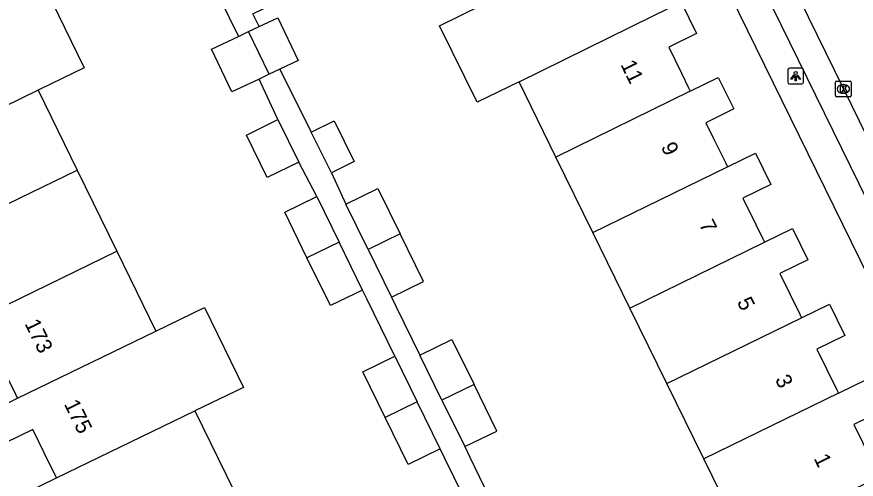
# Model space of a CAD drawing. Extents: x 160457 to 162082, y 388340 to 389736.
# Drawn here: x 160940.3 to 160994.2, y 388958.7 to 388988.4 of the extents above; entities that cross this region are included whole.
import ezdxf

# ---------------------------------------------------------------- set-up
doc = ezdxf.new("R2010")
doc.units = 0
for name, color, linetype in [('IMGEO_Kolk', 7, 'Continuous'), ('IMGEO_Lichtpunt', 7, 'Continuous'), ('IMGEO_Pand', 7, 'Continuous'), ('IMGEO_Pand_nummerreeks', 7, 'Continuous'), ('IMGEO_Rijbaan_lokaal_open', 7, 'Continuous'), ('IMGEO_Voetpad_open', 7, 'Continuous')]:
    doc.layers.add(name, color=color, linetype=linetype)

msp = doc.modelspace()

# ---------------------------------------------------------------- linework, layer by layer
at = {"layer": 'IMGEO_Kolk'}
for p, q in [((160992.907, 388983.31), (160992.907, 388984.162)), ((160992.982, 388984.236), (160993.834, 388984.236)), ((160993.395, 388984.016), (160993.42, 388984.016)), ((160993.908, 388984.162), (160993.908, 388983.31)), ((160993.418, 388983.456), (160993.393, 388983.456)), ((160993.834, 388983.236), (160992.982, 388983.236))]:
    msp.add_line(p, q, dxfattribs=at)
for points in [[(160992.907, 388983.31), (160992.907, 388984.162)], [(160992.982, 388984.236), (160993.834, 388984.236)], [(160993.228, 388983.936), (160993.351, 388983.936), (160993.351, 388983.785), (160993.481, 388983.936), (160993.645, 388983.936), (160993.499, 388983.785), (160993.652, 388983.536), (160993.5, 388983.536), (160993.415, 388983.7), (160993.351, 388983.633), (160993.351, 388983.536), (160993.228, 388983.536), (160993.228, 388983.936)], [(160993.908, 388984.162), (160993.908, 388983.31)], [(160993.834, 388983.236), (160992.982, 388983.236)]]:
    msp.add_lwpolyline(points, dxfattribs=at)
for centre, start, end in [((160992.984, 388984.16), 91.552, 178.448), ((160992.984, 388984.16), 91.552, 178.448), ((160993.832, 388984.16), 1.552, 88.448), ((160993.832, 388984.16), 1.552, 88.448), ((160992.984, 388983.312), 181.552, 268.448), ((160992.984, 388983.312), 181.552, 268.448), ((160993.832, 388983.312), 271.552, 358.448), ((160993.832, 388983.312), 271.552, 358.448)]:
    msp.add_arc(centre, 0.0765, start, end, dxfattribs=at)
for centre, major_axis, ratio, start_param, end_param in [((160993.394, 388983.736), (-0.387, 0.002), 0.722429, 4.712389, 7.853982), ((160993.419, 388983.736), (-0.39, 0.002), 0.717154, 1.570796, 4.712389)]:
    msp.add_ellipse(centre, major_axis=major_axis, ratio=ratio, start_param=start_param, end_param=end_param, dxfattribs=at)
at = {"layer": 'IMGEO_Lichtpunt'}
for p, q in [((160989.845, 388984.968), (160989.845, 388984.161)), ((160989.845, 388984.968), (160989.845, 388984.161)), ((160990.747, 388985.063), (160989.939, 388985.063)), ((160990.747, 388985.063), (160989.939, 388985.063)), ((160990.841, 388984.161), (160990.841, 388984.968)), ((160990.841, 388984.161), (160990.841, 388984.968)), ((160989.939, 388984.067), (160990.747, 388984.067)), ((160989.939, 388984.067), (160990.747, 388984.067))]:
    msp.add_line(p, q, dxfattribs=at)
for points in [[(160990.219, 388984.632), (160990.258, 388984.604), (160990.07, 388984.342), (160990.032, 388984.369), (160990.219, 388984.632)], [(160990.321, 388984.584), (160990.368, 388984.584), (160990.368, 388984.262), (160990.321, 388984.262), (160990.321, 388984.584)], [(160990.431, 388984.604), (160990.469, 388984.631), (160990.656, 388984.369), (160990.617, 388984.341), (160990.431, 388984.604)]]:
    msp.add_lwpolyline(points, dxfattribs=at)
msp.add_circle((160990.344, 388984.766), 0.0994, dxfattribs=at)
for centre, start, end in [((160989.939, 388984.968), 90, 180), ((160989.939, 388984.968), 90, 180), ((160990.747, 388984.968), 0, 90), ((160990.747, 388984.968), 0, 90), ((160989.939, 388984.161), 180, 270), ((160989.939, 388984.161), 180, 270), ((160990.747, 388984.161), 270, 0), ((160990.747, 388984.161), 270, 360)]:
    msp.add_arc(centre, 0.0946, start, end, dxfattribs=at)
at = {"layer": 'IMGEO_Pand'}
for points in [[(160939.203, 388988.758), (160942.168, 388990.207), (160944.664, 388985.102), (160941.789, 388983.697), (160941.699, 388983.653)], [(160981.201, 388988.431), (160982.995, 388989.312), (160983.985, 388987.294), (160982.191, 388986.414), (160983.003, 388984.76), (160983.468, 388983.812), (160983.578, 388983.587)], [(160972.581, 388984.199), (160969.887, 388982.881), (160967.481, 388987.799), (160970.175, 388989.117)], [(160955.888, 388987.746), (160957.085, 388988.314), (160958.392, 388985.556), (160957.228, 388985.004)], [(160972.581, 388984.199), (160981.201, 388988.431)], [(160955.204, 388987.422), (160955.888, 388987.746)], [(160955.897, 388984.373), (160954.146, 388983.543), (160952.839, 388986.301), (160954.557, 388987.115)], [(160954.557, 388987.115), (160955.204, 388987.422)], [(160956.54, 388984.678), (160955.204, 388987.422)], [(160957.228, 388985.004), (160956.54, 388984.678)], [(160956.54, 388984.678), (160955.897, 388984.373)], [(160983.578, 388983.587), (160985.372, 388984.468), (160986.363, 388982.449), (160984.568, 388981.569), (160985.067, 388980.552), (160985.849, 388978.958), (160985.958, 388978.736)], [(160974.952, 388979.353), (160972.581, 388984.199)], [(160941.699, 388983.653), (160932.808, 388979.319)], [(160941.699, 388983.653), (160944.206, 388978.524)], [(160983.578, 388983.587), (160974.952, 388979.353)], [(160958.44, 388979.035), (160956.414, 388978.038), (160955.071, 388980.768), (160957.096, 388981.765)], [(160957.096, 388981.765), (160958.44, 388979.035)], [(160959.237, 388980.968), (160960.706, 388981.695), (160961.998, 388979.081), (160960.529, 388978.355)], [(160960.529, 388978.355), (160959.237, 388980.968)], [(160985.958, 388978.736), (160987.754, 388979.615), (160988.74, 388977.605), (160986.945, 388976.724), (160987.777, 388975.029), (160988.227, 388974.113), (160988.337, 388973.889)], [(160977.323, 388974.508), (160974.952, 388979.353)], [(160935.313, 388974.204), (160944.206, 388978.524)], [(160944.206, 388978.524), (160946.748, 388973.322)], [(160977.323, 388974.508), (160985.958, 388978.736)], [(160961.463, 388976.339), (160963.521, 388977.344), (160964.94, 388974.438)], [(160958.963, 388972.89), (160957.534, 388975.814), (160959.59, 388976.818)], [(160959.59, 388976.818), (160961.023, 388973.889)], [(160962.885, 388973.429), (160961.463, 388976.339)], [(160988.337, 388973.889), (160990.131, 388974.769), (160991.122, 388972.751), (160989.327, 388971.87), (160989.968, 388970.565), (160990.608, 388969.259), (160990.717, 388969.037)], [(160964.94, 388974.438), (160962.885, 388973.429)], [(160964.381, 388970.367), (160966.438, 388971.372), (160964.94, 388974.438)], [(160979.698, 388969.653), (160977.323, 388974.508)], [(160961.023, 388973.889), (160958.963, 388972.89)], [(160962.524, 388970.818), (160961.023, 388973.889)], [(160979.698, 388969.653), (160988.337, 388973.889)], [(160937.86, 388968.998), (160946.748, 388973.322)], [(160946.748, 388973.322), (160949.26, 388968.183)], [(160962.885, 388973.429), (160964.381, 388970.367)], [(160962.524, 388970.818), (160960.467, 388969.813), (160958.963, 388972.89)], [(160990.717, 388969.037), (160992.513, 388969.916), (160993.503, 388967.897), (160991.709, 388967.016), (160992.347, 388965.716), (160992.985, 388964.415), (160993.094, 388964.192)], [(160949.26, 388968.183), (160952.377, 388969.695), (160954.886, 388964.561), (160951.768, 388963.052)], [(160982.069, 388964.807), (160979.698, 388969.653)], [(160940.37, 388963.871), (160940.257, 388964.101), (160939.28, 388966.097), (160938.846, 388966.983), (160937.051, 388966.104), (160936.063, 388968.123), (160937.86, 388968.998)], [(160982.069, 388964.807), (160990.717, 388969.037)], [(160940.37, 388963.871), (160949.26, 388968.183)], [(160966.212, 388966.641), (160968.27, 388967.646), (160969.688, 388964.744)], [(160963.977, 388962.631), (160962.545, 388965.561), (160964.602, 388966.566)], [(160964.602, 388966.566), (160966.038, 388963.629)], [(160967.632, 388963.736), (160966.212, 388966.641)], [(160993.094, 388964.192), (160994.89, 388965.07), (160995.876, 388963.061), (160994.078, 388962.183), (160995.724, 388958.813), (160987.069, 388954.587), (160984.44, 388959.961)], [(160969.688, 388964.744), (160967.632, 388963.736)], [(160969.089, 388960.754), (160971.146, 388961.759), (160969.688, 388964.744)], [(160984.44, 388959.961), (160982.069, 388964.807)], [(160942.875, 388958.75), (160942.761, 388958.984), (160942.46, 388959.6), (160941.355, 388961.857), (160939.56, 388960.978), (160938.571, 388962.998), (160940.37, 388963.871)], [(160993.094, 388964.192), (160984.44, 388959.961)], [(160966.038, 388963.629), (160963.977, 388962.631)], [(160967.515, 388960.608), (160966.038, 388963.629)], [(160967.632, 388963.736), (160969.089, 388960.754)], [(160942.875, 388958.75), (160951.768, 388963.052)], [(160951.768, 388963.052), (160954.272, 388957.931)], [(160967.515, 388960.608), (160965.458, 388959.602), (160963.977, 388962.631)], [(160945.384, 388953.626), (160945.27, 388953.859), (160944.631, 388955.164), (160943.86, 388956.74), (160942.064, 388955.861), (160941.076, 388957.88), (160942.875, 388958.75)]]:
    msp.add_lwpolyline(points, dxfattribs=at)
at = {"layer": 'IMGEO_Rijbaan_lokaal_open'}
msp.add_lwpolyline([(160984.223, 389002.492), (160985.444, 389000), (160993.409, 388983.736), (161000, 388970.263), (161001.751, 388966.684), (161003.536, 388963.113)], dxfattribs=at)
at = {"layer": 'IMGEO_Voetpad_open'}
for points in [[(160977.985, 388999.523), (160978.97, 389000), (160980.708, 389000.842), (160981.121, 389000), (161000, 388961.47), (161000.234, 388960.992)], [(161000.59, 388965.032), (161000, 388966.237), (160983.825, 388999.266)], [(160955.888, 388987.746), (160955.488, 388988.566), (160967.576, 388994.43)], [(160952.424, 388991.475), (160952.742, 388990.824), (160954.557, 388987.115)], [(160957.228, 388985.004), (160959.237, 388980.968)], [(160957.096, 388981.765), (160955.897, 388984.373)], [(160959.59, 388976.818), (160958.44, 388979.035)], [(160960.529, 388978.355), (160961.463, 388976.339)], [(160964.602, 388966.566), (160962.802, 388970.25), (160962.524, 388970.818)], [(160964.381, 388970.367), (160964.669, 388969.778), (160966.212, 388966.641)], [(160969.089, 388960.754), (160969.418, 388960.08), (160970.94, 388956.941)], [(160969.624, 388956.297), (160967.813, 388959.998), (160967.515, 388960.608)]]:
    msp.add_lwpolyline(points, dxfattribs=at)

# ---------------------------------------------------------------- texts
at = {"layer": 'IMGEO_Pand_nummerreeks'}
for s, rotation, p in [('11', 296.1267, (160979.075, 388985.31)), ('9', 296.1267, (160981.669, 388980.021)), ('7', 296.1267, (160984.111, 388975.042)), ('5', 296.1267, (160986.553, 388970.063)), ('173', 296.0522, (160940.81, 388968.665)), ('3', 296.1267, (160988.995, 388965.084)), ('175', 296.0522, (160943.339, 388963.493)), ('1', 296.1267, (160991.486, 388960.004))]:
    msp.add_text(s, height=1, rotation=rotation, dxfattribs=at).set_placement(p)

doc.saveas('drawing.dxf')
